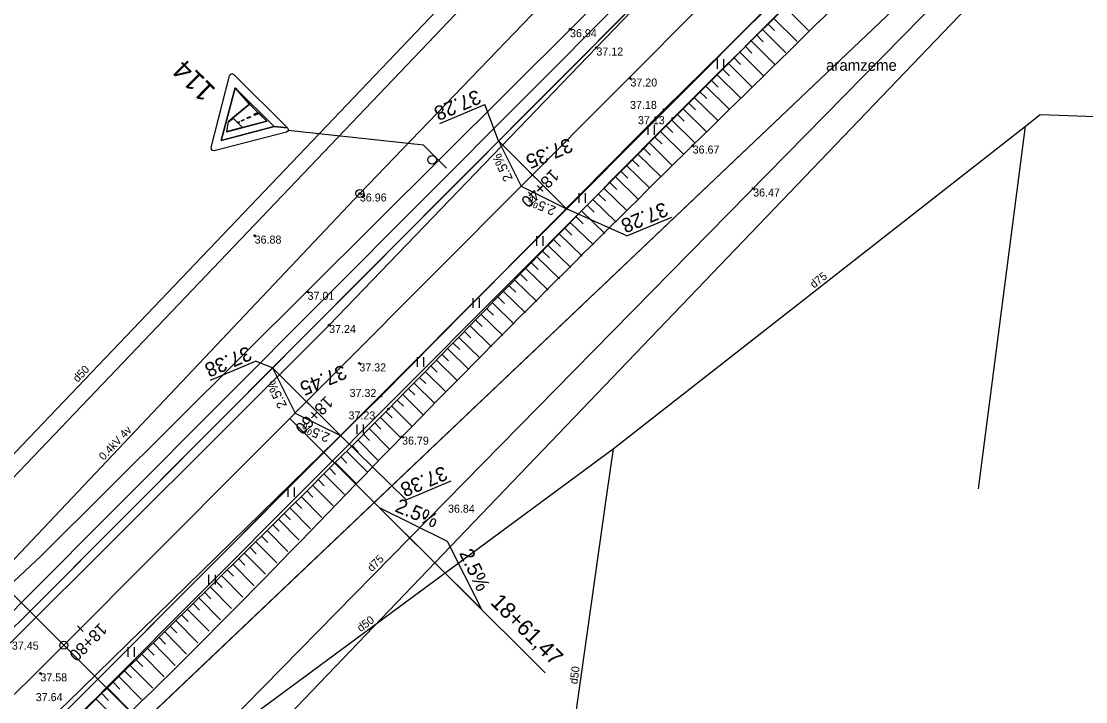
# Model space of a CAD drawing. Extents: x 469981 to 472086, y 246785 to 247785.
# Drawn here: x 470276.9 to 470343.4, y 247002.1 to 247044.6 of the extents above; entities that cross this region are included whole.
import ezdxf

# ---------------------------------------------------------------- set-up
doc = ezdxf.new("R2010")
doc.units = 0
for name, color, linetype in [('0_922', 7, 'Continuous'), ('0_Asfalta_mala', 7, 'Continuous'), ('0_Asfalta_Nomale', 7, 'Continuous'), ('0_Ruut_Braukt', 7, 'Continuous'), ('0_Ruut_nomale', 7, 'Continuous'), ('0_vertikals', 7, 'Continuous'), ('0_vertkals_cipari', 7, 'Continuous'), ('0_Virazjas', 7, 'Continuous'), ('0_Ziimes', 7, 'Continuous'), ('21', 7, 'Continuous'), ('5_patagas', 7, 'Continuous'), ('6_piketaza', 7, 'Continuous'), ('CELI_CMAL_####_####_#', 7, 'Continuous'), ('DREN_VADP_####_####_#', 7, 'Continuous'), ('DREN_VADP_####_TKST_#', 7, 'Continuous'), ('DREN_VADP_KLKT_####_#', 7, 'Continuous'), ('DREN_VADP_KLKT_TKST_#', 7, 'Continuous'), ('ELEK_ELEM_####_####_#', 7, 'Continuous'), ('ELEK_VADV_ZSPR_####_#', 7, 'Continuous'), ('ELEK_VADV_ZSPR_TKST_#', 7, 'Continuous'), ('RAMI_UZMR_####_####_#', 7, 'Continuous'), ('RELJ_AATZ_####_TKST_#', 7, 'Continuous'), ('RELJ_ELEM_####_####_#', 7, 'Continuous'), ('RELJ_NOGA_####_####_#', 7, 'Continuous'), ('RELJ_NOGL_####_####_#', 7, 'Continuous'), ('ROBZ_IERR_####_####_#', 7, 'Continuous'), ('ROBZ_PROJ_####_####_#', 7, 'Continuous'), ('TERT_ELEM_####_####_#', 7, 'Continuous'), ('TERT_IZMT_####_TKST_#', 7, 'Continuous')]:
    doc.layers.add(name, color=color, linetype=linetype)

msp = doc.modelspace()

# ---------------------------------------------------------------- linework, layer by layer
msp.add_circle((470279.553, 247005.63), 0.25)
at = {"layer": '0_922'}
msp.add_line((470338.394, 247064.708), (470279.553, 247005.63), dxfattribs=at)
msp.add_arc((470102.422, 247182.052), 250, 303.58428, 315.11501, dxfattribs=at)
at = {"layer": '0_Asfalta_mala'}
for p, q in [((470336.269, 247066.825), (470277.427, 247007.747)), ((470340.52, 247062.591), (470281.679, 247003.513))]:
    msp.add_line(p, q, dxfattribs=at)
for radius in [247, 253]:
    msp.add_arc((470102.422, 247182.052), radius, 303.58428, 315.11501, dxfattribs=at)
at = {"layer": '0_Asfalta_Nomale'}
for p, q in [((470335.737, 247067.355), (470276.896, 247008.277)), ((470341.051, 247062.062), (470282.21, 247002.984))]:
    msp.add_line(p, q, dxfattribs=at)
msp.add_arc((470102.422, 247182.052), 253.75, 303.58428, 315.11501, dxfattribs=at)
at = {"layer": '0_Ruut_Braukt'}
for p, q in [((470336.269, 247066.825), (470277.427, 247007.747)), ((470281.679, 247003.513), (470340.52, 247062.591))]:
    msp.add_line(p, q, dxfattribs=at)
for radius in [247, 253]:
    msp.add_arc((470102.422, 247182.052), radius, 303.58428, 315.11501, dxfattribs=at)
at = {"layer": '0_Ruut_nomale'}
for p, q in [((470335.737, 247067.355), (470276.896, 247008.277)), ((470277.427, 247007.747), (470336.269, 247066.825)), ((470340.52, 247062.591), (470281.679, 247003.513)), ((470282.21, 247002.984), (470341.051, 247062.062))]:
    msp.add_line(p, q, dxfattribs=at)
for radius in [246.25, 247, 253, 253.75]:
    msp.add_arc((470102.422, 247182.052), radius, 303.58428, 315.11501, dxfattribs=at)
at = {"layer": '0_vertikals'}
for p, q in [((470303.029, 247038.227), (470305.839, 247039.403)), ((470306.693, 247037.131), (470305.839, 247039.403)), ((470314.708, 247031.205), (470310.944, 247032.897)), ((470314.708, 247031.205), (470317.518, 247032.382)), ((470288.711, 247022.2), (470291.522, 247023.377)), ((470292.579, 247022.96), (470291.522, 247023.377)), ((470300.933, 247014.722), (470296.831, 247018.726)), ((470300.933, 247014.722), (470303.743, 247015.898))]:
    msp.add_line(p, q, dxfattribs=at)
for points in [[(470306.693, 247037.131), (470308.113, 247034.305), (470310.944, 247032.897)], [(470292.579, 247022.96), (470293.999, 247020.135), (470296.831, 247018.726)]]:
    msp.add_lwpolyline(points, close=True, dxfattribs=at)
at = {"layer": '0_Virazjas'}
for p, q in [((470309.614, 247003.917), (470293.667, 247019.801)), ((470295.141, 246990.105), (470279.553, 247005.63))]:
    msp.add_line(p, q, dxfattribs=at)
msp.add_lwpolyline([(470305.65, 247007.866), (470303.52, 247012.104), (470299.273, 247014.217)], close=True, dxfattribs=at)
at = {"layer": '0_Ziimes'}
for q in [(470293.56, 247037.796), (470303.453, 247035.434)]:
    msp.add_line((470302.012, 247036.869), q, dxfattribs=at)
for points in [[(470293.56, 247037.796), (470293.52, 247037.725), (470293.467, 247037.69), (470288.95, 247036.525), (470288.839, 247036.535), (470288.768, 247036.611), (470288.765, 247036.721), (470289.903, 247041.207), (470289.918, 247041.246), (470289.935, 247041.273), (470289.945, 247041.285), (470290.016, 247041.326), (470290.095, 247041.326), (470290.165, 247041.286), (470293.518, 247037.946), (470292.69, 247038.035), (470290.259, 247040.457), (470289.389, 247037.152), (470292.69, 247038.035), (470293.518, 247037.946), (470293.56, 247037.875)], [(470292.69, 247038.035), (470289.389, 247037.152), (470290.259, 247040.457), (470291.155, 247039.428), (470289.82, 247038.333), (470289.717, 247037.721), (470289.727, 247037.699), (470292.227, 247038.36), (470291.155, 247039.428), (470290.259, 247040.457)], [(470291.223, 247038.627), (470291.019, 247038.534), (470290.983, 247038.57), (470291.181, 247038.669)], [(470291.727, 247038.857), (470291.466, 247038.738), (470291.417, 247038.786), (470291.671, 247038.914)], [(470289.717, 247037.721), (470290.639, 247037.983), (470290.673, 247037.95), (470290.715, 247037.963), (470290.419, 247038.258), (470290.517, 247038.303), (470290.494, 247038.326), (470290.399, 247038.278), (470290.108, 247038.568), (470290.077, 247038.543), (470290.11, 247038.51), (470289.841, 247038.305), (470289.82, 247038.333)], [(470290.11, 247038.51), (470289.841, 247038.305), (470289.82, 247038.333), (470290.077, 247038.543)], [(470290.792, 247038.475), (470290.824, 247038.444), (470290.655, 247038.367), (470290.629, 247038.393)], [(470290.673, 247037.95), (470289.727, 247037.699), (470289.717, 247037.721), (470290.639, 247037.983)]]:
    msp.add_lwpolyline(points, close=True, dxfattribs=at)
for points in [[(470290.259, 247040.457), (470292.69, 247038.035), (470289.389, 247037.152), (470290.259, 247040.457)], [(470292.227, 247038.36), (470290.715, 247037.963), (470290.419, 247038.258), (470290.517, 247038.303), (470290.494, 247038.326), (470290.399, 247038.278), (470290.108, 247038.568), (470291.155, 247039.428), (470291.671, 247038.914), (470291.417, 247038.786), (470291.466, 247038.738), (470291.727, 247038.857), (470292.227, 247038.36)], [(470290.108, 247038.568), (470290.399, 247038.278), (470290.494, 247038.326), (470290.517, 247038.303), (470290.419, 247038.258), (470290.715, 247037.963), (470292.227, 247038.36), (470291.727, 247038.857), (470291.466, 247038.738), (470291.417, 247038.786), (470291.671, 247038.914), (470291.155, 247039.428), (470290.108, 247038.568)], [(470291.223, 247038.627), (470291.019, 247038.534), (470290.983, 247038.57), (470291.181, 247038.669), (470291.223, 247038.627)], [(470291.223, 247038.627), (470291.019, 247038.534), (470290.983, 247038.57), (470291.181, 247038.669), (470291.223, 247038.627)], [(470290.11, 247038.51), (470289.841, 247038.305), (470289.82, 247038.333), (470290.077, 247038.543), (470290.11, 247038.51)], [(470290.824, 247038.444), (470290.655, 247038.367), (470290.629, 247038.393), (470290.792, 247038.475), (470290.824, 247038.444)], [(470290.824, 247038.444), (470290.655, 247038.367), (470290.629, 247038.393), (470290.792, 247038.475), (470290.824, 247038.444)], [(470290.673, 247037.95), (470289.727, 247037.699), (470289.717, 247037.721), (470290.639, 247037.983), (470290.673, 247037.95)]]:
    msp.add_lwpolyline(points, dxfattribs=at)
msp.add_circle((470302.55, 247035.952), 0.27, dxfattribs=at)
at = {"layer": '21'}
msp.add_line((470338.394, 247064.708), (470279.553, 247005.63), dxfattribs=at)
msp.add_arc((470102.422, 247182.052), 250, 303.58428, 315.11501, dxfattribs=at)
at = {"layer": '5_patagas'}
msp.add_lwpolyline([(470279.553, 247005.63), (470265.382, 247019.744)], dxfattribs=at)
at = {"layer": '6_piketaza'}
for points in [[(470308.996, 247034.837), (470308.642, 247035.19)], [(470294.882, 247020.667), (470294.528, 247021.02)], [(470280.768, 247006.496), (470280.414, 247006.849)]]:
    msp.add_lwpolyline(points, dxfattribs=at)
at = {"layer": 'CELI_CMAL_####_####_#'}
for points in [[(470207.251, 246955.004), (470220.145, 246963.116), (470261.486, 246992.424), (470276.308, 247005.858), (470296.122, 247025.635), (470312.816, 247042.969), (470330.98, 247061.836), (470346.394, 247077.324), (470364.172, 247092.272), (470374.754, 247099.764), (470384.938, 247106.322), (470390.015, 247108.873), (470395.699, 247111.348), (470409.875, 247117.262), (470415.428, 247119.375), (470428.615, 247124.712), (470444.307, 247130.298), (470466.241, 247137.389), (470487.751, 247143.859), (470509.15, 247149.677), (470533.329, 247156.368), (470558.982, 247163.161), (470583.723, 247169.81), (470606.354, 247175.581)], [(470440.723, 247107.99), (470440.084, 247118.844), (470439.302, 247119.794), (470438.459, 247120.205), (470437.434, 247120.771), (470435.683, 247121.111), (470417.849, 247114.314), (470398.184, 247106.061), (470376.912, 247095.329), (470368.488, 247089.418), (470350.85, 247073.72), (470334.429, 247056.212), (470317.045, 247039.09), (470299.359, 247021.199), (470279.758, 247002.025), (470265.741, 246988.964), (470242.76, 246971.543), (470223.686, 246958.587), (470209.766, 246949.279)]]:
    msp.add_lwpolyline(points, dxfattribs=at)
at = {"layer": 'DREN_VADP_####_####_#'}
for points in [[(470344.895, 247104.752), (470352.43, 247097.297), (470267.889, 247008.665), (470215.45, 246973.641)], [(470336.679, 247015.399), (470339.607, 247038.062)], [(470278.779, 246972.124), (470280.321, 246981.315), (470282.587, 246994.817), (470313.858, 247017.896)], [(470313.858, 247017.896), (470313.452, 247015.034), (470310.481, 246994.08)]]:
    msp.add_lwpolyline(points, dxfattribs=at)
at = {"layer": 'DREN_VADP_KLKT_####_#'}
for points in [[(470355.84, 247029.317), (470356.44, 247045.884), (470357.293, 247069.467), (470322.272, 247033.825), (470311.427, 247022.787), (470278.296, 246989.068), (470265.457, 246976.001), (470248.264, 246964.754), (470217.931, 246944.913)], [(470313.858, 247017.896), (470324.297, 247026.072), (470339.607, 247038.062), (470340.533, 247038.787), (470358.465, 247038.13), (470367.518, 247037.799)]]:
    msp.add_lwpolyline(points, dxfattribs=at)
at = {"layer": 'ELEK_ELEM_####_####_#'}
for radius in [0.25, 0.0225]:
    msp.add_circle((470298.042, 247033.852), radius, dxfattribs=at)
at = {"layer": 'ELEK_VADV_ZSPR_####_#'}
for p, q in [((470327.629, 247064.607), (470298.042, 247033.852)), ((470298.042, 247033.852), (470268.498, 247002.594))]:
    msp.add_line(p, q, dxfattribs=at)
at = {"layer": 'RAMI_UZMR_####_####_#'}
for points in [[(470081.833, 246858.073), (470071.225, 246873.795), (470075.411, 246878.04), (470140.155, 246920.953), (470236.136, 246982.998), (470257.83, 246999.315), (470274.171, 247013.774), (470358.465, 247102.148), (470367.97, 247107.52), (470388.133, 247118.916), (470465.996, 247150.017), (470560.64, 247175.144), (470793.366, 247232.231)], [(470682.857, 247179.693), (470601.924, 247155.957), (470538.749, 247139.954), (470448.7, 247112.965), (470443.256, 247108.572), (470439.042, 247107.166), (470426.399, 247105.409), (470390.93, 247093.141), (470379.516, 247082.95), (470369.859, 247080.841), (470357.567, 247068.014), (470285.914, 246993.254), (470269.057, 246978.845), (470246.406, 246963.908), (470178.978, 246918.441), (470154.395, 246901.045), (470104.604, 246871.942), (470081.833, 246858.073)]]:
    msp.add_lwpolyline(points, dxfattribs=at)
at = {"layer": 'RELJ_ELEM_####_####_#'}
for centre in [(470311.167, 247044.116), (470312.816, 247042.969), (470314.939, 247041.034), (470317.045, 247039.09), (470317.592, 247038.544), (470318.825, 247036.845), (470322.605, 247034.162), (470298.042, 247033.852), (470291.469, 247031.221), (470294.775, 247027.709), (470296.122, 247025.635), (470298.01, 247023.237), (470299.359, 247021.199), (470299.823, 247020.383), (470300.677, 247018.663), (470302.079, 247013.567), (470278.088, 247003.875)]:
    msp.add_circle(centre, 0.05, dxfattribs=at)
at = {"layer": 'RELJ_NOGA_####_####_#'}
for p, q in [((470324.562, 247045.539), (470326.057, 247044.039)), ((470323.854, 247044.833), (470325.348, 247043.336)), ((470323.146, 247044.127), (470324.638, 247042.633)), ((470323.5, 247044.48), (470323.948, 247044.031)), ((470322.439, 247043.42), (470323.93, 247041.929)), ((470322.793, 247043.773), (470323.24, 247043.325)), ((470321.732, 247042.712), (470323.221, 247041.226)), ((470322.086, 247043.066), (470322.532, 247042.619)), ((470321.026, 247042.005), (470322.514, 247040.523)), ((470321.379, 247042.358), (470321.825, 247041.913)), ((470320.673, 247041.65), (470321.119, 247041.206)), ((470319.967, 247040.942), (470320.413, 247040.499)), ((470320.32, 247041.296), (470321.805, 247039.818)), ((470319.263, 247040.232), (470319.707, 247039.791)), ((470319.615, 247040.587), (470321.098, 247039.114)), ((470318.559, 247039.522), (470319.003, 247039.083)), ((470318.911, 247039.877), (470320.391, 247038.41)), ((470317.856, 247038.811), (470318.299, 247038.373)), ((470318.207, 247039.167), (470319.685, 247037.704)), ((470317.153, 247038.099), (470317.595, 247037.663)), ((470317.504, 247038.455), (470318.98, 247037)), ((470316.452, 247037.386), (470316.893, 247036.953)), ((470316.802, 247037.743), (470318.275, 247036.294)), ((470315.751, 247036.673), (470316.19, 247036.241)), ((470316.101, 247037.03), (470317.569, 247035.588)), ((470315.401, 247036.316), (470316.863, 247034.882)), ((470314.701, 247035.602), (470316.158, 247034.175)), ((470315.051, 247035.959), (470315.489, 247035.53)), ((470314.001, 247034.887), (470315.452, 247033.469)), ((470314.351, 247035.245), (470314.787, 247034.818)), ((470313.302, 247034.172), (470314.746, 247032.761)), ((470313.652, 247034.53), (470314.086, 247034.105)), ((470312.603, 247033.457), (470314.04, 247032.055)), ((470312.953, 247033.815), (470313.385, 247033.393)), ((470311.905, 247032.741), (470313.334, 247031.347)), ((470312.254, 247033.099), (470312.684, 247032.68)), ((470311.207, 247032.025), (470312.628, 247030.64)), ((470311.556, 247032.383), (470311.984, 247031.966)), ((470310.858, 247031.667), (470311.283, 247031.253)), ((470310.16, 247030.951), (470310.583, 247030.539)), ((470310.509, 247031.309), (470311.922, 247029.933)), ((470309.463, 247030.234), (470309.882, 247029.825)), ((470309.811, 247030.593), (470311.215, 247029.225)), ((470308.765, 247029.518), (470309.182, 247029.112)), ((470309.114, 247029.876), (470310.509, 247028.517)), ((470308.067, 247028.802), (470308.482, 247028.398)), ((470308.416, 247029.16), (470309.802, 247027.809)), ((470307.369, 247028.085), (470307.781, 247027.684)), ((470307.718, 247028.443), (470309.096, 247027.101)), ((470306.671, 247027.369), (470307.081, 247026.97)), ((470307.02, 247027.727), (470308.389, 247026.393)), ((470306.322, 247027.011), (470307.683, 247025.685)), ((470305.624, 247026.295), (470306.976, 247024.976)), ((470305.973, 247026.653), (470306.38, 247026.256)), ((470304.926, 247025.58), (470306.269, 247024.267)), ((470305.275, 247025.937), (470305.679, 247025.543)), ((470304.227, 247024.864), (470305.561, 247023.559)), ((470304.576, 247025.222), (470304.978, 247024.83)), ((470303.527, 247024.15), (470304.855, 247022.851)), ((470303.877, 247024.507), (470304.276, 247024.116)), ((470302.827, 247023.436), (470304.147, 247022.141)), ((470303.177, 247023.793), (470303.574, 247023.403)), ((470302.127, 247022.722), (470303.44, 247021.432)), ((470302.477, 247023.078), (470302.872, 247022.691)), ((470301.777, 247022.365), (470302.169, 247021.979)), ((470301.075, 247021.652), (470301.466, 247021.267)), ((470301.426, 247022.009), (470302.732, 247020.723)), ((470300.373, 247020.94), (470300.762, 247020.556)), ((470300.724, 247021.296), (470302.025, 247020.014)), ((470299.67, 247020.229), (470300.058, 247019.845)), ((470300.022, 247020.584), (470301.317, 247019.305)), ((470298.967, 247019.518), (470299.353, 247019.135)), ((470299.319, 247019.873), (470300.61, 247018.595)), ((470298.262, 247018.809), (470298.648, 247018.425)), ((470298.615, 247019.163), (470299.902, 247017.886)), ((470297.557, 247018.1), (470297.942, 247017.716)), ((470297.91, 247018.454), (470299.194, 247017.175)), ((470296.851, 247017.392), (470297.236, 247017.007)), ((470297.204, 247017.746), (470298.488, 247016.464)), ((470296.498, 247017.038), (470297.782, 247015.754)), ((470295.79, 247016.331), (470297.076, 247015.043)), ((470296.144, 247016.684), (470296.53, 247016.299)), ((470295.083, 247015.624), (470296.371, 247014.332)), ((470295.437, 247015.977), (470295.823, 247015.59)), ((470294.374, 247014.918), (470295.666, 247013.621)), ((470294.728, 247015.271), (470295.115, 247014.883)), ((470293.665, 247014.213), (470294.962, 247012.909)), ((470294.02, 247014.566), (470294.408, 247014.175)), ((470292.956, 247013.509), (470294.257, 247012.197)), ((470293.311, 247013.861), (470293.7, 247013.468)), ((470292.246, 247012.804), (470293.553, 247011.485)), ((470292.601, 247013.156), (470292.992, 247012.762)), ((470291.535, 247012.1), (470292.849, 247010.774)), ((470291.89, 247012.452), (470292.284, 247012.055)), ((470291.18, 247011.749), (470291.575, 247011.349)), ((470290.469, 247011.046), (470290.866, 247010.644)), ((470290.824, 247011.397), (470292.145, 247010.062)), ((470289.758, 247010.343), (470290.157, 247009.938)), ((470290.113, 247010.694), (470291.441, 247009.349)), ((470289.046, 247009.64), (470289.448, 247009.233)), ((470289.402, 247009.991), (470290.738, 247008.638)), ((470288.334, 247008.938), (470288.739, 247008.528)), ((470288.69, 247009.289), (470290.034, 247007.926)), ((470287.622, 247008.236), (470288.029, 247007.823)), ((470287.978, 247008.587), (470289.331, 247007.215)), ((470286.91, 247007.533), (470287.32, 247007.118)), ((470287.266, 247007.884), (470288.628, 247006.504)), ((470286.198, 247006.832), (470286.61, 247006.413)), ((470286.554, 247007.183), (470287.923, 247005.792)), ((470285.485, 247006.13), (470285.9, 247005.709)), ((470285.842, 247006.481), (470287.22, 247005.082)), ((470284.773, 247005.428), (470285.19, 247005.004)), ((470285.129, 247005.779), (470286.516, 247004.371)), ((470284.417, 247005.077), (470285.812, 247003.661)), ((470283.704, 247004.375), (470285.108, 247002.951)), ((470284.061, 247004.726), (470284.481, 247004.3)), ((470282.992, 247003.673), (470284.404, 247002.241)), ((470283.348, 247004.024), (470283.771, 247003.596)), ((470282.28, 247002.971), (470283.699, 247001.532)), ((470282.636, 247003.322), (470283.061, 247002.892)), ((470281.568, 247002.269), (470282.994, 247000.824)), ((470281.924, 247002.62), (470282.351, 247002.187))]:
    msp.add_line(p, q, dxfattribs=at)
msp.add_spline([(470120.845, 246890.769), (470123.591, 246892.466), (470150.351, 246909.177), (470171.26, 246922.106), (470191.149, 246935.734), (470210.204, 246948.514), (470224.202, 246958.074), (470243.113, 246970.411), (470266.522, 246987.913), (470280.536, 247001.251), (470299.823, 247020.383), (470317.592, 247038.544), (470334.877, 247055.828), (470351.425, 247073.192), (470366.151, 247085.967)], degree=3, dxfattribs=at)
at = {"layer": 'RELJ_NOGL_####_####_#'}
msp.add_spline([(470122.047, 246889.925), (470124.645, 246891.606), (470151.263, 246908.028), (470171.623, 246921.498), (470191.873, 246934.822), (470224.882, 246957.282), (470243.432, 246969.856), (470267.182, 246986.981), (470282.015, 246999.84), (470300.677, 247018.663), (470318.825, 247036.845), (470336.227, 247054.122), (470352.943, 247071.373), (470367.141, 247084.447)], degree=3, dxfattribs=at)
at = {"layer": 'ROBZ_IERR_####_####_#'}
for points in [[(470310.127, 246974.356), (470275.956, 246992.729), (470371.503, 247083.47), (470396.219, 247097.502), (470431.624, 247112.202), (470468.364, 247124.23), (470636.973, 247175.147), (470640.03, 247134.708)], [(470335.002, 247137.782), (470368.265, 247098.262), (470361.554, 247094.257), (470278.124, 247011.202), (470269.149, 247002.795), (470222.435, 247031.786)]]:
    msp.add_lwpolyline(points, dxfattribs=at)
at = {"layer": 'ROBZ_PROJ_####_####_#'}
for points in [[(471398.351, 247372.094), (471346.741, 247338.478), (471133.176, 247205.05), (471108.425, 247194.786), (471087.339, 247189.709), (471023.306, 247181.157), (470962.604, 247185.245), (470905.63, 247205.857), (470878.75, 247214.454), (470852.344, 247217.039), (470815.743, 247215.147), (470778.583, 247209.26), (470718.669, 247194.633), (470636.973, 247175.147), (470468.364, 247124.23), (470431.624, 247112.202), (470396.219, 247097.502), (470371.503, 247083.47), (470275.956, 246992.729), (470152.342, 246907.761), (470066.737, 246851.23)], [(470062.774, 246863.479), (470070.591, 246868.587), (470253.618, 246988.247), (470269.149, 247002.795), (470278.124, 247011.202), (470361.554, 247094.257), (470368.265, 247098.262), (470383.103, 247107.116), (470421.395, 247122.632), (470438.432, 247129.536), (470474.818, 247141.882), (470613.752, 247179.765), (470688.303, 247197.106)]]:
    msp.add_lwpolyline(points, dxfattribs=at)
at = {"layer": 'TERT_ELEM_####_####_#'}
for p, q in [((470320.376, 247041.638), (470320.376, 247042.238)), ((470320.776, 247041.638), (470320.776, 247042.238)), ((470316.054, 247037.509), (470316.054, 247038.109)), ((470316.454, 247037.509), (470316.454, 247038.109)), ((470311.733, 247033.27), (470311.733, 247033.87)), ((470312.133, 247033.27), (470312.133, 247033.87)), ((470309.089, 247030.575), (470309.089, 247031.175)), ((470309.489, 247030.575), (470309.489, 247031.175)), ((470305.123, 247026.704), (470305.123, 247027.304)), ((470305.523, 247026.704), (470305.523, 247027.304)), ((470301.646, 247023.029), (470301.646, 247023.629)), ((470302.046, 247023.029), (470302.046, 247023.629)), ((470297.875, 247018.815), (470297.875, 247019.415)), ((470298.275, 247018.815), (470298.275, 247019.415)), ((470293.566, 247014.894), (470293.566, 247015.494)), ((470293.966, 247014.894), (470293.966, 247015.494)), ((470288.619, 247009.422), (470288.619, 247010.022)), ((470289.019, 247009.422), (470289.019, 247010.022)), ((470283.575, 247004.914), (470283.575, 247005.514)), ((470283.975, 247004.914), (470283.975, 247005.514))]:
    msp.add_line(p, q, dxfattribs=at)

# ---------------------------------------------------------------- texts
at = {"layer": '0_vertkals_cipari'}
for s, height, rotation, p in [('37.28', 0.9, 202.71113, (470305.363, 247040.36)), ('37.35', 0.9, 202.71113, (470311.097, 247037.349)), ('2.5%', 0.5993, 115.96454, (470307.619, 247034.775)), ('2.5%', 0.5993, 157.17681, (470310.338, 247032.997)), ('37.28', 0.9, 202.71113, (470317.042, 247033.338)), ('37.38', 0.9, 202.71113, (470291.045, 247024.333)), ('37.45', 0.9, 202.71113, (470296.984, 247023.179)), ('2.5%', 0.5993, 115.96454, (470293.506, 247020.604)), ('2.5%', 0.5993, 157.17681, (470296.224, 247018.827)), ('37.38', 0.9, 202.71113, (470303.267, 247016.854))]:
    msp.add_text(s, height=height, rotation=rotation, dxfattribs=at).set_placement(p)
at = {"layer": '0_Virazjas'}
for s, height, rotation, p in [('2.5%', 0.899, 337.17681, (470300.175, 247014.006)), ('2.5%', 0.899, 295.53214, (470304.224, 247011.391)), ('18+61,47', 1, 315.11501, (470306.144, 247008.247))]:
    msp.add_text(s, height=height, rotation=rotation, dxfattribs=at).set_placement(p)
at = {"layer": '0_Ziimes'}
msp.add_text('114', height=1.25, rotation=135.11501, dxfattribs=at).set_placement((470289.095, 247040.344))
at = {"layer": '6_piketaza'}
for s, p in [('18+40', (470310.038, 247035.424)), ('18+60', (470295.925, 247021.253)), ('18+80', (470281.811, 247007.083))]:
    msp.add_text(s, height=0.75, rotation=225.11501, dxfattribs=at).set_placement(p)
at = {"layer": 'DREN_VADP_####_TKST_#'}
for rotation, p in [(46.35329, (470280.42, 247022.019)), (36.42872, (470298.091, 247006.445)), (81.9299, (470311.62, 247003.178))]:
    msp.add_text('d50', height=0.5, rotation=rotation, dxfattribs=at).set_placement(p)
at = {"layer": 'DREN_VADP_KLKT_TKST_#'}
for rotation, p in [(38.06825, (470326.398, 247027.907)), (45.50412, (470298.801, 247010.193))]:
    msp.add_text('d75', height=0.5, rotation=rotation, dxfattribs=at).set_placement(p)
at = {"layer": 'ELEK_VADV_ZSPR_TKST_#'}
msp.add_text('0.4kV 4v', height=0.5, rotation=46.61429, dxfattribs=at).set_placement((470282.046, 247017.146))
at = {"layer": 'RELJ_AATZ_####_TKST_#'}
for s, p in [('36.94', (470311.167, 247043.616)), ('37.12', (470312.816, 247042.469)), ('37.20', (470314.939, 247040.534)), ('37.18', (470314.918, 247039.135)), ('37.13', (470315.409, 247038.179)), ('36.67', (470318.825, 247036.345)), ('36.47', (470322.605, 247033.662)), ('36.96', (470298.042, 247033.352)), ('36.88', (470291.469, 247030.721)), ('37.01', (470294.775, 247027.209)), ('37.24', (470296.122, 247025.135)), ('37.32', (470298.01, 247022.737)), ('37.32', (470297.4, 247021.143)), ('37.23', (470297.333, 247019.739)), ('36.79', (470300.677, 247018.163)), ('36.84', (470303.546, 247013.913)), ('37.45', (470276.308, 247005.358)), ('37.58', (470278.088, 247003.375)), ('37.64', (470277.799, 247002.141))]:
    msp.add_text(s, height=0.5, dxfattribs=at).set_placement(p)
at = {"layer": 'TERT_IZMT_####_TKST_#'}
msp.add_text('aramzeme', height=0.7, dxfattribs=at).set_placement((470327.158, 247041.515))

doc.saveas('drawing.dxf')
